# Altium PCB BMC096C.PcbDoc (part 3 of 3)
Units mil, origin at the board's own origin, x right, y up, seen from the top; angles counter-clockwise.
Board outline 5500 x 3200 mil, 4 copper layers (Top Layer, Signal Layer 1, Signal Layer 2, Bottom Layer), stack 61.6 mil thick; 174 components, 74 nets, 402 pads, 1110 vias.
Unrouted connection lines stored in the file: 741.
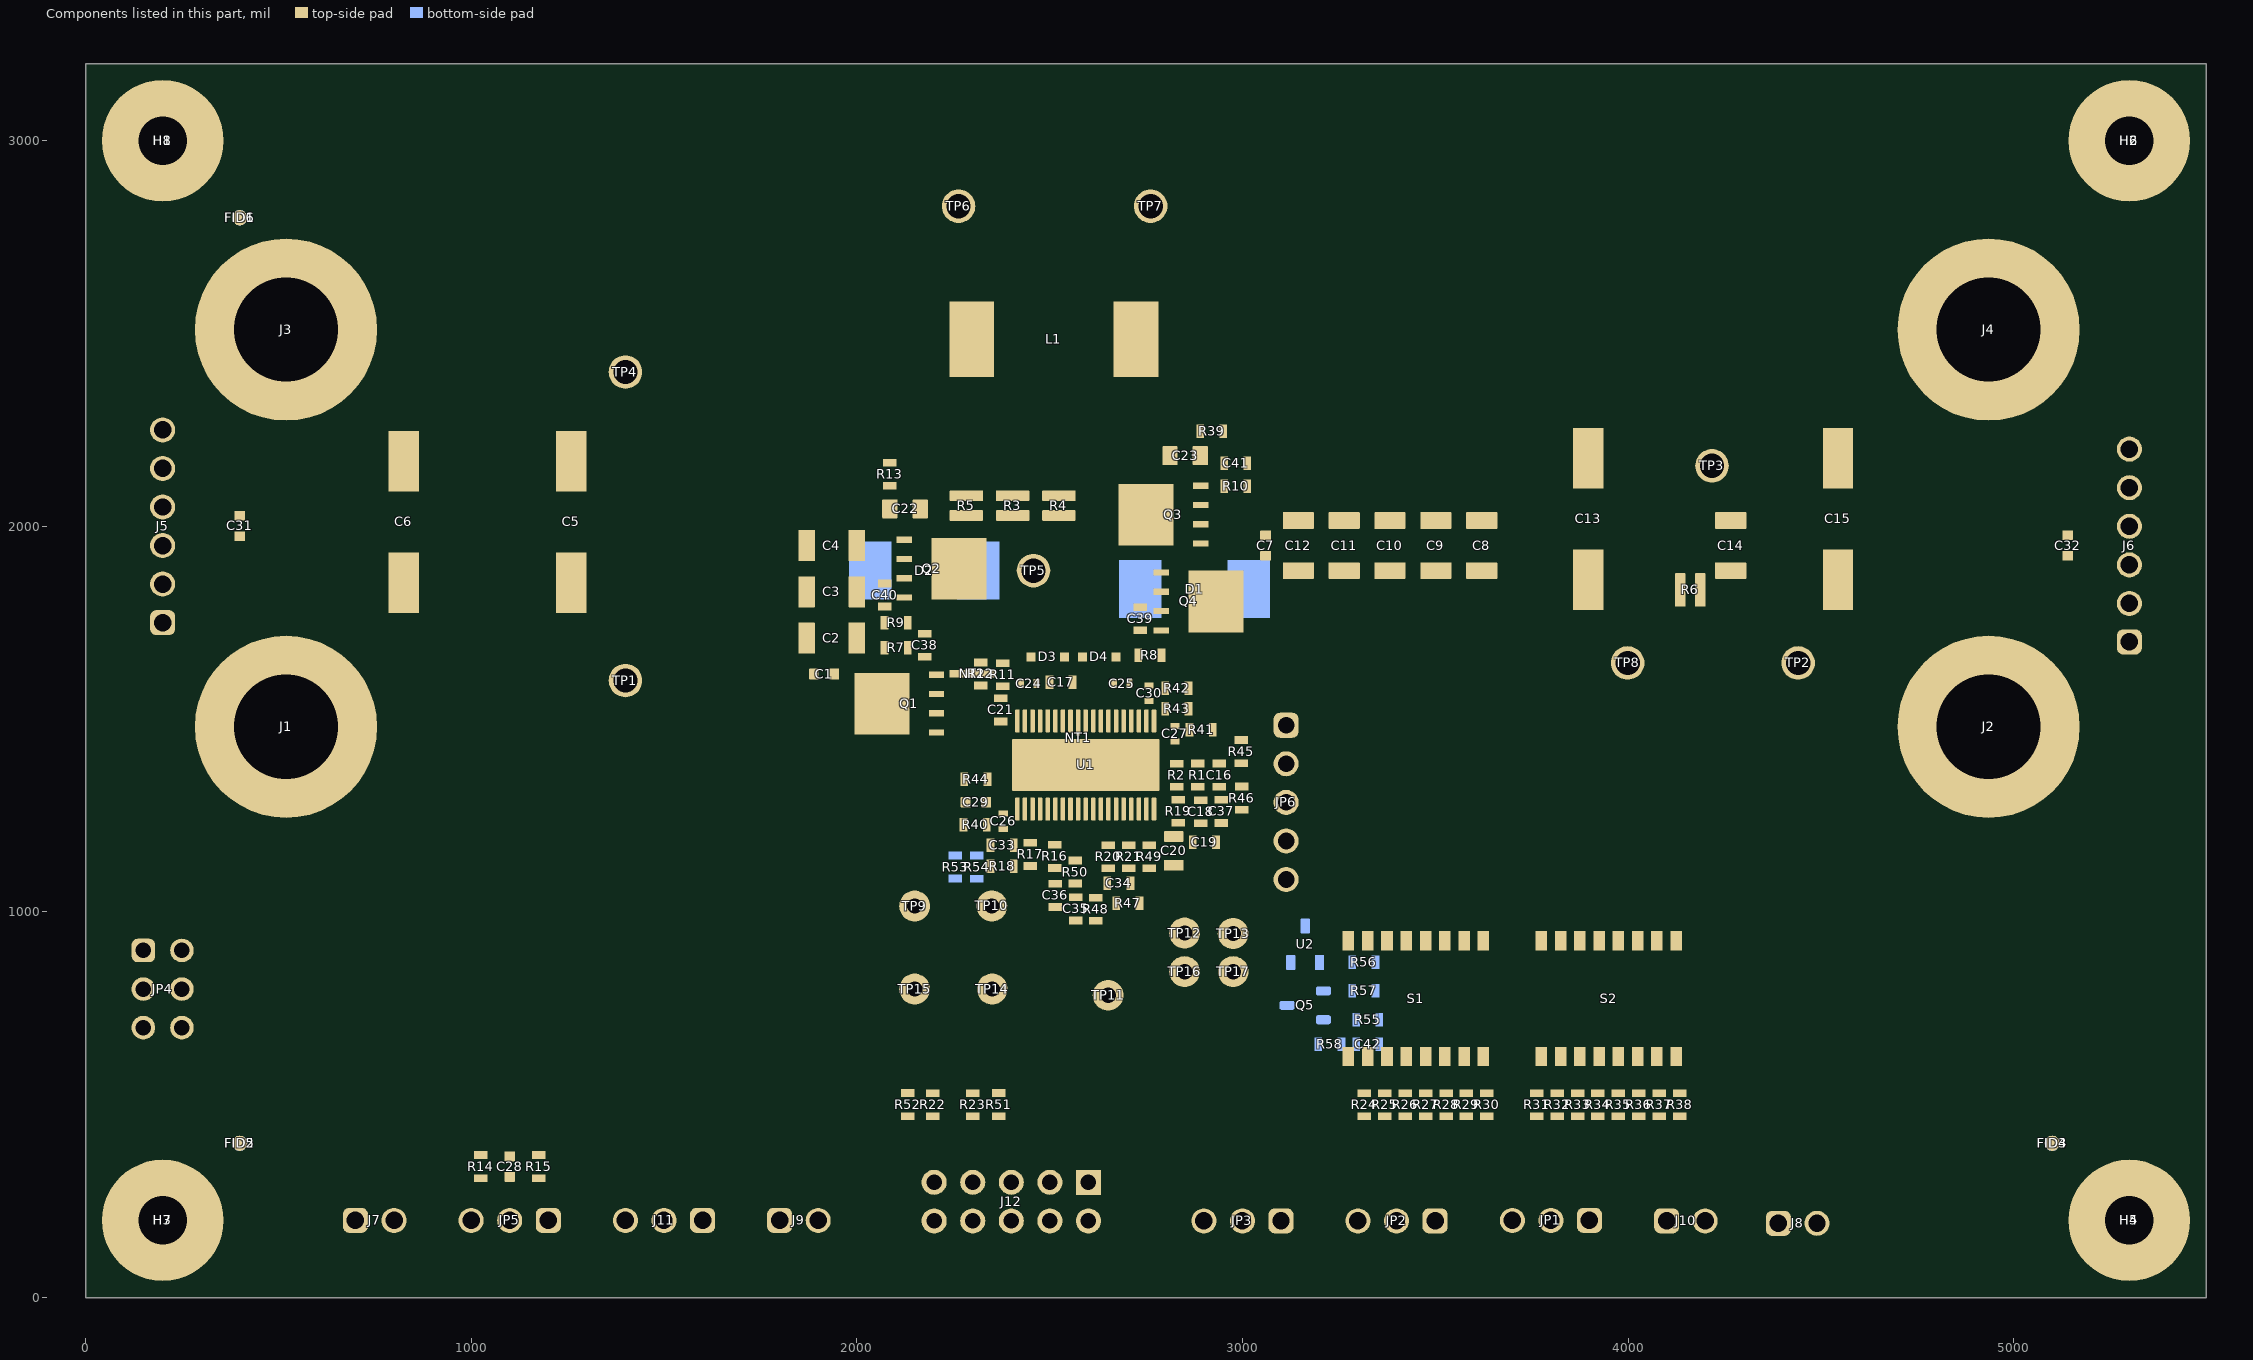
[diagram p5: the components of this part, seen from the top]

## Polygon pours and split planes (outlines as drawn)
NetC7_1 on Top Layer "TOP_LAYER_NETC7_1_P022" (solid, pour order 22): 3045.12,1944.99 4134.26,1945 cw(c4134.26,1929.75) 4149.52,1929.75 4149.52,1590.78 cw(c4121.78,1590.77) 4121.77,1563.03 2976.92,1563.04 cw(c2976.92,1676.95) 2863,1676.95 2863,1916.8 cw(c2876.2,1916.8) 2876.2,1930 3008.91,1930 ccw(c3008.91,1950.82) 3023.64,1936.1 cw(c3045.1,1914.64)
GND on Top Layer "TOP_LAYER_GND_P105" (solid, remove dead copper, pour order 105): 2411.18,1729.57 2698.43,1729.57 cw(c2698.43,1718) 2710,1718 2710,1513.56 2401.09,1513.56 2399.47,1717.76 cw(c2411.18,1717.85)
NetL1_1 on Top Layer "TOP_LAYER_NETL1_1_P021" (solid, pour order 21): 2439.03,2210.31 2595.02,2210.31 cw(c2595.03,2197.83) 2607.5,2197.83 2607.5,2065.28 cw(c2595.78,2065.28) 2595.78,2053.55 2210.26,2053.32 cw(c2210.25,2075.11) 2188.51,2076.74 cw(c2184.99,2101.56) 2161.23,2093.56 2161.23,2899.92 cw(c2173.85,2899.92) 2173.85,2912.54 2396.66,2912.54 cw(c2396.66,2899.47) 2409.73,2899.47 2409.73,2239.6 ccw(c2439.03,2239.6)
AGND on Top Layer "TOP_LAYER_AGND_P087" (solid, pour order 87): 0,1170 1836.16,1170 ccw(c1836.16,1292.93) 1923.09,1206.01 2263.77,1546.68 4143.31,1546.68 cw(c4143.31,1493.53) 4180.9,1531.11 4530.94,1181.04 5500,1181.04 5500,0 0,0
NetC22_2 on Top Layer "TOP_LAYER_NETC22_2_P067" (solid, remove dead copper, pour order 67): 2117.19,2061.84 2117.19,2035.55 ccw(c2162.32,2035.55) 2130.41,2003.64 2140.76,1993.28 2149,1985.05 cw(c2129.93,1965.98) 2156.9,1965.98 2156.9,1467.5 ccw(c2172.39,1467.5) 2172.39,1452 2230.25,1452 ccw(c2230.25,1484.72) 2253.39,1461.58 2274.94,1483.13 ccw(c2234.3,1523.77) 2291.77,1523.77 2291.77,1720.07 cw(c2321.7,1720.07) 2321.7,1750 2584.35,1750 ccw(c2584.35,1773.02) 2607.36,1773.02 2607.36,2020.89 ccw(c2584.97,2020.89) 2584.97,2043.28 2248.18,2043.28 cw(c2248.18,2092.76) 2213.2,2057.77 ccw(c2172.56,2017.14) 2172.55,2074.61 2129.96,2074.61 ccw(c2129.96,2061.84)
SW2 on Top Layer "TOP_LAYER_SW2_P019" (solid, pour order 19): 2636.76,1751.97 2832.96,1751.97 ccw(c2832.96,1768.54) 2849.53,1768.54 2849.53,2896.35 ccw(c2833.35,2896.36) 2833.35,2912.54 2636.56,2912.54 ccw(c2636.56,2894.19) 2618.22,2894.19 2618.22,1770.51 ccw(c2636.76,1770.51)
VIN on Top Layer "TOP_LAYER_VIN_P035" (solid, pour order 35): 1910.08,1982.04 1910.08,1662.97 ccw(c1928.12,1662.97) 1928.12,1644.94 2121.37,1644.94 cw(c2121.37,1630.12) 2136.18,1630.19 2136.96,1447.03 1910.55,1220.63 cw(c1834.2,1296.98) 1834.2,1189 0,1189 0,1989.64 1902.48,1989.64 cw(c1902.48,1982.04)
GND on Top Layer "TOP_LAYER_GND_P071" (solid, pour order 71): 0,3200 5500,3200 5500,1961.07 3038.58,1961.07 ccw(c3038.58,1920.9) 3010.18,1949.3 cw(c2999.05,1960.43) 2999.05,1944.7 2874.89,1944.7 cw(c2874.89,1949.59) 2870,1949.59 2870,2890.15 ccw(c2835.01,2890.15) 2835.01,2925.14 2633.22,2925.14 ccw(c2633.22,2899.43) 2607.5,2899.42 2607.5,2242.24 cw(c2590.26,2242.24) 2590.26,2225 2441.33,2225 cw(c2441.33,2242.49) 2423.84,2242.5 2423.84,2905.28 ccw(c2404.11,2905.28) 2404.11,2925 2173.69,2925 ccw(c2173.69,2896.76) 2145.45,2896.76 2145.45,1650.95 1922.11,1650.95 1922.11,1992.46 ccw(c1913.76,1992.46) 1913.75,2000.81 0,2000.81
VOUT on Top Layer "TOP_LAYER_VOUT_P024" (solid, pour order 24): 4173.03,1594.62 4173.03,1930.34 cw(c4187.69,1930.34) 4187.69,1945 5500,1945 5500,1196 4580.52,1196 cw(c4580.52,1298.35) 4508.15,1225.98 4196.74,1537.4 cw(c4253.96,1594.62)
AGND on Signal Layer 1 "SIGNAL_LAYER_1_AGND_P100" (solid, pour order 100): -3.94,1170.33 1883.14,1170.33 2216.83,1504.02 2888.75,1503.8 ccw(c2888.76,1531.21) 2908.14,1511.82 cw(c2993.09,1426.87) 2993.09,1547.01 4139.37,1547.01 cw(c4139.38,1493.89) 4176.96,1531.44 4499.24,1209.13 ccw(c4566.25,1276.14) 4566.25,1181.37 5496.06,1181.37 5496.06,0.33 -3.94,0.33
GND on Signal Layer 1 "SIGNAL_LAYER_1_GND_P106" (solid, remove dead copper, pour order 106): 2302.71,1728.98 2842.03,1728.98 2842.03,1531.8 cw(c2823.78,1531.8) 2823.78,1513.56 2321.84,1513.56 cw(c2321.84,1532.68) 2302.71,1532.68
VOUT on Signal Layer 1 "SIGNAL_LAYER_1_VOUT_P103" (solid, pour order 103): 4173.03,1594.62 4173.03,1899.2 cw(c4202.83,1899.2) 4202.83,1929 5500,1929 5500,1196 4580.52,1196 cw(c4580.52,1298.35) 4508.15,1225.98 4196.74,1537.4 cw(c4253.96,1594.62)
GND on Signal Layer 1 "SIGNAL_LAYER_1_GND_P098" (solid, pour order 98): 0,3200 5500,3200 5500,1955 3082.67,1955 3075.17,1947.5 2886.53,1947.5 cw(c2886.53,1964.03) 2870,1964.03 2870,2890.15 ccw(c2835.01,2890.15) 2835.01,2925.14 2633.22,2925.14 ccw(c2633.21,2899.43) 2607.5,2899.42 2607.5,2242.24 cw(c2590.27,2242.24) 2590.26,2225 2441.33,2225 cw(c2441.33,2242.49) 2423.84,2242.5 2423.84,2905.28 ccw(c2404.11,2905.28) 2404.11,2925 2173.69,2925 ccw(c2173.69,2896.76) 2145.45,2896.76 2145.45,1664.69 2026.67,1664.55 cw(c2026.61,1706.18) 1997.13,1676.79 1979.27,1694.71 cw(c2034.96,1750.2) 1956.34,1750.2 1956.34,2011.85 ccw(c1932.65,2011.85) 1932.65,2035.55 0,2035.55
SW2 on Signal Layer 1 "SIGNAL_LAYER_1_SW2_P094" (solid, pour order 94): 2636.76,1751.97 2802.07,1751.97 ccw(c2802.07,1772.11) 2822.22,1772.11 2822.22,2086.35 cw(c2847.39,2086.35) 2829.59,2104.15 2839.32,2113.88 ccw(c2812.48,2140.71) 2850.44,2140.76 2849.53,2896.36 ccw(c2833.35,2896.36) 2833.35,2912.54 2636.56,2912.54 ccw(c2636.56,2894.2) 2618.22,2894.19 2618.22,1770.51 ccw(c2636.76,1770.51)
NetL1_1 on Signal Layer 1 "SIGNAL_LAYER_1_NETL1_1_P092" (solid, pour order 92): 2439.03,2210.31 2595.02,2210.31 cw(c2595.03,2197.83) 2607.5,2197.83 2607.5,2065.28 cw(c2595.78,2065.28) 2595.78,2053.55 2210.26,2053.32 cw(c2210.25,2075.11) 2195.9,2058.71 2168.48,2082.69 cw(c2184.99,2101.56) 2161.23,2093.56 2161.23,2899.92 cw(c2173.85,2899.92) 2173.85,2912.54 2396.66,2912.54 cw(c2396.66,2899.47) 2409.73,2899.47 2409.73,2239.6 ccw(c2439.03,2239.6)
NetC22_2 on Signal Layer 1 "SIGNAL_LAYER_1_NETC22_2_P076" (solid, remove dead copper, pour order 76): 2117.19,2061.84 2117.19,2035.55 ccw(c2162.32,2035.55) 2130.41,2003.64 2140.76,1993.28 2149,1985.05 cw(c2129.93,1965.98) 2156.9,1965.98 2156.9,1467.5 ccw(c2172.39,1467.5) 2172.39,1452 2230.25,1452 ccw(c2230.25,1484.72) 2253.39,1461.58 2274.94,1483.13 ccw(c2234.3,1523.77) 2291.77,1523.77 2291.77,1720.07 cw(c2321.7,1720.07) 2321.7,1750 2584.35,1750 ccw(c2584.35,1773.02) 2607.36,1773.02 2607.36,2020.89 ccw(c2584.97,2020.89) 2584.97,2043.28 2248.18,2043.28 cw(c2248.18,2092.76) 2213.2,2057.77 ccw(c2172.56,2017.14) 2172.55,2074.61 2129.96,2074.61 ccw(c2129.96,2061.84)
VIN on Signal Layer 1 "SIGNAL_LAYER_1_VIN_P055" (solid, pour order 55): 1910.08,1971.55 1910.08,1662.97 ccw(c1928.12,1662.97) 1928.12,1644.94 2115.05,1644.94 cw(c2115.05,1623.77) 2136.21,1623.86 2136.87,1468.16 cw(c2086.16,1467.95) 2122.01,1432.09 1901.65,1211.73 cw(c1846.78,1266.61) 1846.78,1189 0,1189 0,1989.64 1891.99,1989.64 cw(c1891.99,1971.55)
NetC7_1 on Signal Layer 1 "SIGNAL_LAYER_1_NETC7_1_P072" (solid, pour order 72): 2884.91,1927.67 4142.5,1927.67 cw(c4142.5,1908.6) 4161.57,1908.6 4161.57,1602.95 2885.77,1602.95 cw(c2885.77,1614.86) 2873.87,1614.86 2873.87,1916.63 cw(c2884.91,1916.63)
AGND on Bottom Layer "BOTTOM_LAYER_AGND_P113" (solid, pour order 113): -3.94,1170.33 1883.14,1170.33 2216.83,1504.02 2888.75,1503.8 ccw(c2888.76,1531.21) 2908.14,1511.82 cw(c2993.09,1426.87) 2993.09,1547.01 4139.23,1547.01 cw(c4139.38,1493.89) 4176.96,1531.44 4527,1181.37 5496.06,1181.37 5496.06,0.33 -3.94,0.33
GND on Bottom Layer "BOTTOM_LAYER_GND_P108" (solid, remove dead copper, pour order 108): 2321.61,1728.98 2837.53,1728.98 cw(c2837.53,1709.95) 2856.56,1709.95 2856.56,1532.25 cw(c2837.87,1532.25) 2837.87,1513.56 2313.92,1513.56 cw(c2313.92,1524.76) 2302.71,1524.76 2302.71,1710.09 cw(c2321.61,1710.09)
VOUT on Bottom Layer "BOTTOM_LAYER_VOUT_P104" (solid, pour order 104): 4173.03,1594.62 4173.03,1930.34 cw(c4187.69,1930.34) 4187.69,1945 5500,1945 5500,1196 4580.52,1196 cw(c4580.52,1298.35) 4508.15,1225.98 4196.74,1537.4 cw(c4253.96,1594.62)
GND on Bottom Layer "BOTTOM_LAYER_GND_P099" (solid, pour order 99): 0,3200 5500,3200 5500,1960.63 3031.97,1960.63 ccw(c3031.97,1925.67) 3012.75,1954.88 cw(c2988.11,1992.34) 2988.11,1947.5 2887.9,1947.5 cw(c2887.9,1965.4) 2870,1965.4 2870,2890.15 ccw(c2835.01,2890.15) 2835.01,2925.14 2633.22,2925.14 ccw(c2633.22,2899.43) 2607.5,2899.42 2607.5,2242.24 cw(c2590.26,2242.24) 2590.26,2225 2441.33,2225 cw(c2441.33,2242.49) 2423.84,2242.5 2423.84,2905.28 ccw(c2404.11,2905.28) 2404.11,2925 2173.69,2925 ccw(c2173.69,2896.76) 2145.45,2896.76 2145.45,1650.95 1922.11,1650.95 1922.11,1992.46 ccw(c1913.76,1992.46) 1913.75,2000.81 0,2000.81
SW2 on Bottom Layer "BOTTOM_LAYER_SW2_P095" (solid, pour order 95): 2636.76,1751.97 2832.96,1751.97 ccw(c2832.96,1768.54) 2849.53,1768.54 2849.53,2896.35 ccw(c2833.35,2896.36) 2833.35,2912.54 2636.56,2912.54 ccw(c2636.56,2894.19) 2618.22,2894.19 2618.22,1770.51 ccw(c2636.76,1770.51)
NetL1_1 on Bottom Layer "BOTTOM_LAYER_NETL1_1_P093" (solid, pour order 93): 2439.03,2210.31 2595.02,2210.31 cw(c2595.03,2197.83) 2607.5,2197.83 2607.5,2065.28 cw(c2595.78,2065.28) 2595.78,2053.55 2210.26,2053.32 cw(c2210.25,2075.11) 2188.51,2076.74 cw(c2184.99,2101.56) 2161.23,2093.56 2161.23,2899.92 cw(c2173.85,2899.92) 2173.85,2912.54 2396.66,2912.54 cw(c2396.66,2899.47) 2409.73,2899.47 2409.73,2239.6 ccw(c2439.03,2239.6)
NetC22_2 on Bottom Layer "Top Layer-NetC22_2" (solid, remove dead copper, pour order 20): 2117.19,2061.84 2117.19,2035.55 ccw(c2162.32,2035.55) 2130.41,2003.64 2140.76,1993.28 2149,1985.05 cw(c2129.93,1965.98) 2156.9,1965.98 2156.9,1467.5 ccw(c2172.39,1467.5) 2172.39,1452 2230.25,1452 ccw(c2230.25,1484.72) 2253.39,1461.58 2274.94,1483.13 ccw(c2234.3,1523.77) 2291.77,1523.77 2291.77,1720.07 cw(c2321.7,1720.07) 2321.7,1750 2584.35,1750 ccw(c2584.35,1773.02) 2607.36,1773.02 2607.36,2020.89 ccw(c2584.97,2020.89) 2584.97,2043.28 2248.18,2043.28 cw(c2248.18,2092.76) 2213.2,2057.77 ccw(c2172.56,2017.14) 2172.55,2074.61 2129.96,2074.61 ccw(c2129.96,2061.84)
VIN on Bottom Layer "BOTTOM_LAYER_VIN_P078" (solid, pour order 78): 1910.08,1989.64 1910.08,1644.94 2136.12,1644.94 2136.96,1447.03 1878.92,1189 0,1189 0,1989.64
NetC7_1 on Bottom Layer "BOTTOM_LAYER_NETC7_1_P062" (solid, pour order 62): 3042.41,1945 4141.36,1945 cw(c4141.37,1924.8) 4161.57,1924.8 4161.57,1584.22 cw(c4143.89,1584.22) 4143.89,1566.54 2881.88,1566.54 cw(c2881.88,1578.43) 2870,1578.43 2870,1905.77 cw(c2894.23,1905.77) 2894.23,1930 3006.2,1930 ccw(c3006.2,1949.43) 3019.94,1935.69 cw(c3042.41,1913.22)
AGND on Signal Layer 2 "SIGNAL_LAYER_2_AGND_P111" (solid, pour order 111): 36.77,1152.24 1892.17,1152.24 ccw(c1892.17,1228.72) 1946.25,1174.64 2257.54,1485.93 2929.46,1485.7 ccw(c2929.47,1513.12) 2948.85,1493.73 cw(c3033.8,1408.78) 3033.8,1528.92 4179.94,1528.92 cw(c4180.09,1475.8) 4217.67,1513.35 4553.28,1177.71 ccw(c4588.11,1212.54) 4588.11,1163.28 5536.77,1163.28 5536.77,-17.76 36.77,-17.76
GND on Signal Layer 2 "SIGNAL_LAYER_2_GND_P112" (solid, pour order 112): 0,3200 5500,3200 5500,1196.94 4549.63,1196.94 cw(c4549.63,1256.88) 4507.25,1214.5 4209.92,1511.82 2210.35,1511.82 1902.06,1203.79 cw(c1846.27,1259.63) 1846.27,1180.69 0,1180.69

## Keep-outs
Keep-Out Layer:
  text ".Layer_Name" at 577,-858.49 h60

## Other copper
Top Layer:
  pour cut-out: 5258.88,1899.76 ccw(c5300.24,1899.76) 5300.24,1858.41 ccw(c5300.24,1899.76) 5341.59,1899.76 ccw(c5300.24,1899.76) 5300.24,1941.11 ccw(c5300.24,1899.76)
  pour cut-out: 5258.4,2000.28 ccw(c5299.75,2000.28) 5299.75,1958.93 ccw(c5299.75,2000.28) 5341.11,2000.28 ccw(c5299.75,2000.28) 5299.75,2041.63 ccw(c5299.75,2000.28)
  pour cut-out: 158.75,2049.72 ccw(c200.1,2049.72) 200.1,2008.37 ccw(c200.1,2049.72) 241.46,2049.72 ccw(c200.1,2049.72) 200.1,2091.07 ccw(c200.1,2049.72)
  pour cut-out: 158.17,1950.33 ccw(c199.52,1950.33) 199.52,1908.97 ccw(c199.52,1950.33) 240.87,1950.33 ccw(c199.52,1950.33) 199.52,1991.68 ccw(c199.52,1950.33)
  text ".Layer_Name" at 577,-858.49 h60
Signal Layer 1:
  pour cut-out: 1875.85,1679.99 ccw(c1897.35,1679.99) 1897.35,1658.48 ccw(c1897.35,1679.99) 1918.86,1679.99 ccw(c1897.35,1679.99) 1897.35,1701.5 ccw(c1897.35,1679.99)
  pour cut-out: 1950.34,1679.99 ccw(c1971.85,1679.99) 1971.85,1658.48 ccw(c1971.85,1679.99) 1993.36,1679.99 ccw(c1971.85,1679.99) 1971.85,1701.5 ccw(c1971.85,1679.99)
  pour cut-out: 3038.49,1905 ccw(c3060,1905) 3060,1883.49 ccw(c3060,1905) 3081.51,1905 ccw(c3060,1905) 3060,1926.51 ccw(c3060,1905)
  pour cut-out: 4164.13,1786.45 ccw(c4185.64,1786.45) 4185.64,1764.94 ccw(c4185.64,1786.45) 4207.15,1786.45 ccw(c4185.64,1786.45) 4185.64,1807.96 ccw(c4185.64,1786.45)
  pour cut-out: 4114.13,1786.45 ccw(c4135.64,1786.45) 4135.64,1764.94 ccw(c4135.64,1786.45) 4157.15,1786.45 ccw(c4135.64,1786.45) 4135.64,1807.96 ccw(c4135.64,1786.45)
  pour cut-out: 3038.49,1995 ccw(c3060,1995) 3060,1973.49 ccw(c3060,1995) 3081.51,1995 ccw(c3060,1995) 3060,2016.51 ccw(c3060,1995)
  pour cut-out: 5258.88,1899.76 ccw(c5300.24,1899.76) 5300.24,1858.41 ccw(c5300.24,1899.76) 5341.59,1899.76 ccw(c5300.24,1899.76) 5300.24,1941.11 ccw(c5300.24,1899.76)
  pour cut-out: 5258.4,2000.28 ccw(c5299.75,2000.28) 5299.75,1958.93 ccw(c5299.75,2000.28) 5341.11,2000.28 ccw(c5299.75,2000.28) 5299.75,2041.63 ccw(c5299.75,2000.28)
  pour cut-out: 158.75,2049.72 ccw(c200.1,2049.72) 200.1,2008.37 ccw(c200.1,2049.72) 241.46,2049.72 ccw(c200.1,2049.72) 200.1,2091.07 ccw(c200.1,2049.72)
  pour cut-out: 158.17,1950.33 ccw(c199.52,1950.33) 199.52,1908.97 ccw(c199.52,1950.33) 240.87,1950.33 ccw(c199.52,1950.33) 199.52,1991.68 ccw(c199.52,1950.33)
  pour cut-out: 3081.51,1999.28 3081.51,1997.36 3106.87,1972 5253.06,1972 5277.26,1996.21 5296.16,1977.3 5298.2,1977.3 5298.2,1976.42 5263.86,1942.08 3088.72,1942.08 3055.72,1975.08 3055.72,1986.77
  pour cut-out: 4197,1779 4197.82,1778.18 4197.82,1754.06 4185.64,1741.88 4185.64,1636.27 4167.41,1618.04 4147.82,1637.62 4147.82,1643.5 4155.65,1651.33 4155.65,1756.46 4184.19,1785 4186.29,1785
  text ".Layer_Name" at 577.07,-859.59 h60
Signal Layer 2:
  pour cut-out: 1950.34,1679.99 ccw(c1971.85,1679.99) 1971.85,1658.48 ccw(c1971.85,1679.99) 1993.36,1679.99 ccw(c1971.85,1679.99) 1971.85,1701.5 ccw(c1971.85,1679.99)
  pour cut-out: 3038.49,1995.13 ccw(c3060,1995.13) 3060,1973.62 ccw(c3060,1995.13) 3081.51,1995.13 ccw(c3060,1995.13) 3060,2016.64 ccw(c3060,1995.13)
  pour cut-out: 5258.88,1899.76 ccw(c5300.24,1899.76) 5300.24,1858.41 ccw(c5300.24,1899.76) 5341.59,1899.76 ccw(c5300.24,1899.76) 5300.24,1941.11 ccw(c5300.24,1899.76)
  pour cut-out: 5258.4,2000.28 ccw(c5299.75,2000.28) 5299.75,1958.93 ccw(c5299.75,2000.28) 5341.11,2000.28 ccw(c5299.75,2000.28) 5299.75,2041.63 ccw(c5299.75,2000.28)
  pour cut-out: 158.75,2049.72 ccw(c200.1,2049.72) 200.1,2008.37 ccw(c200.1,2049.72) 241.46,2049.72 ccw(c200.1,2049.72) 200.1,2091.07 ccw(c200.1,2049.72)
  pour cut-out: 158.17,1950.33 ccw(c199.52,1950.33) 199.52,1908.97 ccw(c199.52,1950.33) 240.87,1950.33 ccw(c199.52,1950.33) 199.52,1991.68 ccw(c199.52,1950.33)
  text ".Layer_Name" at 575.75,-859.59 h60
Bottom Layer:
  pour cut-out: 1950.34,1679.99 ccw(c1971.85,1679.99) 1971.85,1658.48 ccw(c1971.85,1679.99) 1993.36,1679.99 ccw(c1971.85,1679.99) 1971.85,1701.5 ccw(c1971.85,1679.99)
  pour cut-out: 1875.97,1680.26 ccw(c1897.48,1680.26) 1897.48,1658.75 ccw(c1897.48,1680.26) 1918.99,1680.26 ccw(c1897.48,1680.26) 1897.48,1701.76 ccw(c1897.48,1680.26)
  pour cut-out: 4165.05,1785.33 ccw(c4186.56,1785.33) 4186.56,1763.82 ccw(c4186.56,1785.33) 4208.07,1785.33 ccw(c4186.56,1785.33) 4186.56,1806.83 ccw(c4186.56,1785.33)
  pour cut-out: 4115.05,1785.33 ccw(c4136.56,1785.33) 4136.56,1763.82 ccw(c4136.56,1785.33) 4158.07,1785.33 ccw(c4136.56,1785.33) 4136.56,1806.83 ccw(c4136.56,1785.33)
  pour cut-out: 3038.84,1994.97 ccw(c3060.34,1994.97) 3060.34,1973.46 ccw(c3060.34,1994.97) 3081.85,1994.97 ccw(c3060.34,1994.97) 3060.34,2016.48 ccw(c3060.34,1994.97)
  pour cut-out: 5258.4,2000.28 ccw(c5299.75,2000.28) 5299.75,1958.93 ccw(c5299.75,2000.28) 5341.11,2000.28 ccw(c5299.75,2000.28) 5299.75,2041.63 ccw(c5299.75,2000.28)
  pour cut-out: 5258.88,1899.76 ccw(c5300.24,1899.76) 5300.24,1858.41 ccw(c5300.24,1899.76) 5341.59,1899.76 ccw(c5300.24,1899.76) 5300.24,1941.11 ccw(c5300.24,1899.76)
  pour cut-out: 158.17,1950.33 ccw(c199.52,1950.33) 199.52,1908.97 ccw(c199.52,1950.33) 240.87,1950.33 ccw(c199.52,1950.33) 199.52,1991.68 ccw(c199.52,1950.33)
  pour cut-out: 158.75,2049.72 ccw(c200.1,2049.72) 200.1,2008.37 ccw(c200.1,2049.72) 241.46,2049.72 ccw(c200.1,2049.72) 200.1,2091.07 ccw(c200.1,2049.72)
  text ".Layer_Name" at 577,-858.49 h60

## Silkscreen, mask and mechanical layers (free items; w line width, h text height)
Top Overlay:
  lines w10: 3442.22,1039.95 3618.92,1039.95 3620.57,1041.6 3620.57,1527.57 3619.26,1528.89 3442.22,1528.89 3442.22,1039.95
  text "CSB" at 2216.08,2931 h35
  text "SW2" at 2706,2929 h35
  text "GND" at 4170.29,2252.84 h35
  text "GND" at 279.34,2174.75 h35
  text "GND" at 5146,2131.71 h35
  text "S-" at 279.57,2030.73 h35
  text "S-" at 5180.88,1988.53 h35
  text "S+" at 282.39,1933.37 h35
  text "S+" at 5180.88,1879.92 h35
  text "CSA" at 2546.08,1872 h35
  text "VIN" at 271.64,1785.47 h35
  text "VOUT" at 5112.82,1735.47 h35
  text "4-36V" at 81,1640 h35
  text "16V" at 5263.92,1608.92 h35
  text "Max.10A" at 56,1586.61 h35
  text "Max.9.4A" at 5187.22,1559.78 h35
  text "JP6" at 3474.04,1549.43 h35
  text "ISNSP" at 3928,1512.5 h35
  text "VOUT" at 4383.52,1512.5 h35
  text "AC_A" at 3468.04,1468.17 h35
  text "AC_B" at 3468.04,1376.48 h35
  text "AGND" at 3468.04,1268.64 h35
  text "R_FB" at 3468.04,1164.83 h35
  text "VCC" at 3468.04,1065.79 h35
  text ".PRJ_title" at 4383.92,971.49 h60
  text "SS/" at 2691.75,947.1 h35
  text "COMP" at 3038.46,931.91 h35
  text "VBIAS" at 2056.66,916.91 h35
  text "VCC" at 2295.08,910.91 h35
  text "ATRK" at 2657.86,890.71 h35
  text "'.PRJ_Number'" at 4383.45,889.17 h40
  text "VEXT" at 341.29,886.83 h35
  text "REV..PCB_Rev" at 4384.8,814.58 h40
  text "VIN" at 341.29,786.83 h35
  text "AGND" at 2857.25,743.23 h35
  text "SDA" at 2101.92,702 h35
  text "SCL" at 2316.76,702 h35
  text "VOUT" at 339.29,686.83 h35
  text "SYNC" at 2588,676 h35
  text "VIN" at 1010.4,456 h35 r90
  text "EN/UVLO" at 1110.4,456 h35 r90
  text "GND" at 1219,456 h35 r90
  text "GND" at 819,295.5 h35 r90
  text "VCC" at 1419,295.5 h35 r90
  text "FLT" at 1819,295.5 h35 r90
  text "VEXT" at 719,291.5 h35 r90
  text "IMONOUT" at 1519,291.5 h35 r90
  text "GND" at 1619,288.76 h35 r90
  text "GND" at 1919,285.5 h35 r90
  text "VCC" at 3719,281 h35 r90
  text "MODE" at 3810.4,281 h35 r90
  text "GND" at 3919,281 h35 r90
  text "RT" at 4119,281 h35 r90
  text "GND" at 4219,281 h35 r90
  text "GND" at 4509,279.77 h35 r90
  text "VCC" at 3319,278.69 h35 r90
  text "SYNC" at 3412.9,278.69 h35 r90
  text "GND" at 3514,278.69 h35 r90
  text "VCC" at 2918,273.14 h35 r90
  text "CFG" at 4407.09,271.64 h35 r90
  text "DTRK" at 3014,270.78 h35 r90
  text "GND" at 3119.04,271.17 h35 r90
  text ".Layer_Name" at 577,-858.49 h60
Bottom Overlay:
  text ".Layer_Name" at 577,-858.49 h60
Top Paste:
  text ".Layer_Name" at 577,-858.49 h60
Bottom Paste:
  text ".Layer_Name" at 577,-858.49 h60
Top Solder:
  text ".Layer_Name" at 577,-858.49 h60
  text ".Layer_Name" at 577,-858.49 h60
Bottom Solder:
  text ".Layer_Name" at 577,-858.49 h60
Drill Guide:
  text ".Layer_Name" at 577,-858.49 h60
M1 Board Outline:
  the board outline again, w10
  text ".Layer_Name" at 577,-858.49 h60
M2 Board Dimensions:
  rectangle: 0,-275 125,-150
  rectangle: 125,-400 500,-275
  lines w7: 0,-275 1000,-275 ; 125,-400 125,-150 ; 250,-400 250,-150 ; 500,-400 500,-150 ; 750,-400 750,-150 ; 0,-400 1000,-400 1000,-150 0,-150 0,-400
  text ".Layer_Name" at 577,-858.49 h60
M3 3D STEP Top:
  text ".Layer_Name" at 577,-858.49 h60
M4 3D STEP Bottom:
  text ".Layer_Name" at 577,-858.49 h60
M5 Assembly Top:
  lines w10: -292,-930.17 6308,-930.17 ; -292,-726.83 6310,-726.83 ; -292,-523.5 -292,-1133.5 3713,-1133.5 6310,-1133.5 6310,-523.5 -291.5,-523.5 -291.5,-1133.5 1284,-1133.5 ; 2173,-1133.5 2173,-523.5 ; 3440,-726.83 3440,-523.5 ; 4280,-726.83 4280,-523.5 ; 4902,-1140 4902,-937.17
  text "COMPONENTS MARKED 'DNP' SHOULD NOT BE POPULATED." at 1153.5,-318.5 h60
  text "ASSEMBLY VARIANT:" at 1153,-434 h60
  text ".VariantName" at 2189,-434 h60
  text "PCB VIEWED FROM TOP SIDE" at -228.5,-655.67 h60
  text "BOARD #:" at 2248,-655.67 h60
  text ".PRJ_Number" at 2793.5,-655.67 h60
  text "REV:" at 3638,-655.67 h60
  text ".PCB_Rev" at 3929.5,-655.67 h60
  text "SVN REV:" at 4476,-655.67 h60
  text ".VersionControl_RevNumber" at 4982,-655.67 h60
  text "TID #:" at 2248,-859 h60
  text ".TID" at 2793.5,-859 h60
  text "PLOT NAME =" at -228.5,-1064.34 h60
  text ".plot_File_Name" at 577,-1064.34 h60
  text "GENERATED    :" at 2250,-1064.34 h60
  text ".Print_Date" at 3119.5,-1064.34 h60
  text ".Print_Time" at 3848.5,-1064.34 h60
  text "TEXAS INSTRUMENTS" at 5113,-1064.34 h60
M6 Assembly Bottom:
  lines w10: -292.5,-727.33 6309.5,-727.33 ; -290.5,-930.67 6309.5,-930.67 ; 1115.5,-1140.5 1115.5,-937.67 ; 1737.5,-727.33 1737.5,-524 ; 2577.5,-727.33 2577.5,-524 ; 3844.5,-1134 3844.5,-524 ; 4733.5,-1134 6309,-1134 6309,-524 -292.5,-524 -292.5,-1134 2304.5,-1134 6309.5,-1134 6309.5,-524
  text "COMPONENTS MARKED 'DNP' SHOULD NOT BE POPULATED." at 6102,-318 h60
  text ".VariantName" at 5058,-434 h60
  text "ASSEMBLY VARIANT:" at 6097,-434 h60
  text ".VersionControl_RevNumber" at 1035.5,-656.17 h60
  text "SVN REV:" at 1541.5,-656.17 h60
  text ".PCB_Rev" at 2088,-656.17 h60
  text "REV:" at 2379.5,-656.17 h60
  text ".PRJ_Number" at 3224,-656.17 h60
  text "BOARD #:" at 3769.5,-656.17 h60
  text "PCB VIEWED FROM BOTTOM SIDE" at 6246,-656.17 h60
  text ".TID" at 3224,-859.5 h60
  text "TID #:" at 3769.5,-859.5 h60
  text "TEXAS INSTRUMENTS" at 904.5,-1064.84 h60
  text ".Print_Time" at 2169,-1064.84 h60
  text ".Print_Date" at 2898,-1064.84 h60
  text "GENERATED    :" at 3767.5,-1064.84 h60
  text ".plot_File_Name" at 5440.5,-1064.84 h60
  text "PLOT NAME =" at 6246,-1064.84 h60
M9 Title Sheet:
  lines w10: -491.5,1041.5 -291.5,1041.5 ; -491.5,3416.5 -291.5,3416.5 ; -491.5,5791.5 -291.5,5791.5 ; 2008.5,-1333.5 2008.5,-1133.5 ; 2008.5,7966.5 2008.5,8166.5 ; 4508.5,-1333.5 4508.5,-1133.5 ; 4508.5,7966.5 4508.5,8166.5 ; 6321,-1133.5 6321,-523.5 11303.5,-523.5 ; 7008.5,-1333.5 7008.5,-1133.5 ; 7008.5,7966.5 7008.5,8166.5 ; 9508.5,-1333.5 9508.5,-1133.5 ; 9508.5,7966.5 9508.5,8166.5 ; 11303.5,-1133.5 11303.5,-523.5 ; 11303.5,-823.5 14303.5,-823.5 ; 11303.5,-223.5 14303.5,-223.5 ; 11304.5,370.5 14304.5,370.5 ; 12008.5,-1333.5 12008.5,-1133.5 ; 12008.5,7966.5 12008.5,8166.5 ; 12808.5,-1123.5 12808.5,-523.5 ; 14303.5,-523.5 11303.5,-523.5 ; 14303.5,76.5 11303.5,76.5 ; 14308.5,66.5 14308.5,-1133.5 ; 14308.5,871 11304.5,871 11303.5,871 11303.5,370.5 11303.5,76.5 ; 14308.5,1041.5 14508.5,1041.5 ; 14308.5,3416.5 14508.5,3416.5 ; 14308.5,5791.5 14508.5,5791.5 ; 11303.5,-523.5 11303.5,76.5 ; 14308.5,-1133.5 14308.5,7966.5 -291.5,7966.5 -291.5,-1133.5 14308.5,-1133.5 ; -491.5,-1333.5 -491.5,8166.5 14508.5,8166.5 14508.5,-1333.5 -491.5,-1333.5
  text "1" at 739.84,8036.5 h70
  text "2" at 3235.5,8036.5 h70
  text "3" at 5724.84,8036.5 h70
  text "4" at 8231.51,8036.5 h70
  text "5" at 10730.5,8036.5 h70
  text "6" at 13235.5,8036.5 h70
  text "A" at -416.5,6893.5 h70
  text "A" at 14383.5,6893.5 h70
  text "B" at -416.5,4513.5 h70
  text "B" at 14383.5,4513.5 h70
  text "C" at -416.5,2138.5 h70
  text "C" at 14383.5,2138.5 h70
  text "PROJECT TITLE:" at 11343.5,277.5 h45
  text ".PRJ_Title" at 11393.5,144.17 h70
  text "DESIGNED FOR:" at 11343.5,-23.5 h45
  text ".PRJ_Customer" at 11393.5,-163.5 h70
  text "D" at -416.5,-231.5 h70
  text "D" at 14383.5,-231.5 h70
  text "FILE NAME:" at 11343.5,-323.5 h45
  text ".PCB_File_Name_No_Path" at 11393.5,-443.5 h70
  text "Texas Instruments (TI) and/or its licensors do not warrant the accuracy or completeness of this specification" at 6374,-605.34 h45
  text "ENGINEER:" at 11343.5,-613.5 h45
  text "LAYOUT BY:" at 12848.5,-613.5 h45
  text "or any information contained therein. TI and/or its licensors do not warrant that this design will meet" at 6329.01,-718 h45
  text ".PRJ_Engineer" at 11393.5,-768.49 h70
  text ".PCB_Layout" at 12899,-768.49 h70
  text "the specifications, will be suitable for your application or fit for any particular purpose, or will operate in" at 6329.01,-830.67 h45
  text ".Layer_Name" at 577,-858.49 h60
  text "ALTIUM DESIGNER VERSION:" at 12848.5,-923.5 h45
  text "an implementation. TI and/or its licensors do not warrant that the design is production worthy. You should" at 6329.01,-943.33 h45
  text "completely validate and test your design implementation to confirm the system functionality for your application." at 6374,-1056 h45
  text ".print_Scale" at 11393.5,-1056.83 h70
  text ".Application_BuildNumber" at 12899,-1056.83 h70
  text "1" at 739.84,-1263.5 h70
  text "2" at 3235.5,-1263.5 h70
  text "3" at 5724.84,-1263.5 h70
  text "4" at 8231.51,-1263.5 h70
  text "5" at 10730.5,-1263.5 h70
  text "6" at 13235.5,-1263.5 h70
M10 Fab Notes:
  drawing of 189 lines, arcs and shapes, not listed
  text "DESIGN INFORMATION" at 12382.02,6356.17 h60
  text "MIN. TRACK WIDTH:" at 11737.46,6224.05 h60
  text "8" at 12833.7,6224.05 h60
  text "MIL" at 12988.46,6224.05 h60
  text "7.874" at 12667.32,6102.36 h60
  text "MIN. CLEARANCE:" at 11737.46,6099.92 h60
  text "MIL" at 12988.46,6099.92 h60
  text "19.685" at 12628,5977 h60
  text "MIN. VIA PAD SIZE:" at 11737.46,5975.8 h60
  text "MIL" at 12988.46,5975.8 h60
  text "0.05mm (2MIL)" at 12432.46,5845.9 h60
  text "MINIMUM ANNULAR RING" at 11408.23,5837.67 h60
  text "EXTERNAL" at 13140.46,5837.67 h60
  text "PER" at 11608.23,5727.55 h60
  text "IPC-D-275 CLASS 2 LEVEL C" at 11828.23,5727.54 h60
  text "MIL, HOLES" at 13316.46,5627.07 h60
  text "+/-" at 12924,5618.48 h60
  text "+/-" at 13778,5618.48 h60
  text "REGISTRATION TOLERANCES:" at 11408.23,5617.42 h60
  text "METAL" at 12608,5617.42 h60
  text "5" at 13184.2,5617.42 h60
  text "3" at 14017.2,5617.42 h60
  text "MIL" at 14133.46,5617.42 h60
  text "HOLE SIZE TOLERANCE (UNLESS OTHERWISE SPECIFIED):" at 11408.23,5519.1 h60
  text "+/-" at 13778,5516.23 h60
  text "3" at 14017.2,5515.17 h60
  text "MIL" at 14133.46,5515.17 h60
  text "MATERIAL:" at 11333.46,5377.52 h60
  text "FR-4 High Tg" at 12319.9,5249 h60
  text "X" at 12175.46,5241.01 h60
  text "FR-408" at 11754.46,5236.49 h60
  text "OTHER" at 13242.46,5236.49 h60
  text "62 MIL (1.6mm) +/-10%" at 12074.56,5093.46 h60
  text "X" at 11954.46,5091.01 h60
  text "THICKNESS:" at 11408.23,5085.24 h60
  text "OTHER" at 13359.46,5085.24 h60
  text "TOLERANCE:" at 11408.23,4946.92 h60
  text "X" at 12256.46,4946.92 h60
  text "ANSI IPC-6012 TYPE 3 CLASS 2" at 12434.48,4946.92 h60
  text "OTHER +/-" at 12434.46,4802.73 h60
  text "BOW & TWIST:" at 11408.23,4657.54 h60
  text "X" at 12256.46,4657.54 h60
  text "ANSI IPC-6012 TYPE 3 CLASS 2" at 12434.48,4657.54 h60
  text "OTHER +/-" at 12434.46,4510.85 h60
  text "DRILLING:" at 11333.46,4380.23 h60
  text "NC_DRILL FILES" at 13094.46,4275.04 h60
  text "REFERENCE:" at 11408.23,4271.1 h60
  text "X" at 12065.46,4271.01 h60
  text "AS SHOWN" at 12243.46,4271.1 h60
  text "X" at 12966.46,4271.1 h60
  text "OTHER" at 13392.46,4128.85 h60
  text "PTH COPPER THICKNESS:" at 11407.91,4125.32 h60
  text "X" at 12547.14,4125.32 h60
  text "20-30 um" at 12675.14,4125.32 h60
  text "BOARD FINISH:" at 11333.46,3977.73 h60
  text "SILKSCREEN:" at 11488.68,3867.6 h60
  text "X" at 12446.46,3867.6 h60
  text "TOP" at 12563.46,3867.6 h60
  text "X" at 12956.46,3867.6 h60
  text "BOTTOM" at 13074.46,3867.6 h60
  text "SILKSCREEN COLOR:" at 11488.68,3712.41 h60
  text "X" at 12445.46,3712.41 h60
  text "WHITE" at 12563.46,3712.41 h60
  text "OTHER" at 13074.46,3712.41 h60
  text "X" at 12576.46,3568.96 h60
  text "GREEN" at 12694.46,3568.96 h60
  text "OTHER" at 13312.46,3568.96 h60
  text "SOLDER RESIST COLOR:" at 11488.68,3562.1 h60
  text "X" at 12576.46,3414.71 h60
  text "MATTE" at 12694.46,3414.71 h60
  text "SEMI-GLOSS" at 13312,3414.07 h60
  text "IMMERSION GOLD (ENIG)" at 12394.46,3241.94 h60
  text "ENEPIG" at 13732,3234.72 h60
  text "SURFACE FINISH:" at 11333.46,3233.72 h60
  text "X" at 12216.46,3233.72 h60
  text "IMM. TIN/SILVER OR EQUIV" at 11663,3096.4 h60
  text "OTHER" at 13094.46,3092.47 h60
  text "ARRAY/PANEL:" at 11333.46,2937.09 h60
  text "CUT AND TRIM PER M1 BOARD OUTLINE" at 12394.46,2928.87 h60
  text "N.C. ROUTE" at 12394.46,2792.9 h60
  text "X" at 13082.46,2792.9 h60
  text "V. SCORE" at 13260.46,2792.9 h60
  text "CERTIFICATION:" at 11333.46,2663.77 h60
  text "MATERIALS AND WORKMANSHIP FOR ALL PCBS" at 12058.46,2663.77 h60
  text "TO MEET OR EXCEED THE REQUIREMENTS OF:" at 12058.46,2569.71 h60
  text "X" at 11695.97,2441.08 h60
  text "ANSI IPC-A-600F CLASS ->" at 11823.96,2441.08 h60
  text "X" at 13471.97,2441.08 h60
  text "2" at 13581.96,2441.08 h60
  text "1" at 13266.96,2439.58 h60
  text "3" at 13935.96,2439.58 h60
  text "X" at 12507.97,2293.39 h60
  text "RoHS" at 12635.96,2293.39 h60
  text "OTHER" at 13280.36,2293.39 h60
  text "PER ORDER" at 13677.42,2293.39 h60
  text "ALL BOARDS MUST MEET OR EXCEED UL94-V0 REQUIREMENTS." at 11361,2139.57 h60
  text "PCB MUST BEAR THE UL94V-0 UL REGISTERED MATERIAL ID NUMBER" at 11361,2023.5 h60
  text "ADDITIONAL REQUIREMENTS:" at 11333.46,1854.08 h60
  text "MICROSECTION:" at 11408.23,1746.95 h60
  text "YES" at 12313.96,1746.95 h60
  text "REQUIRED" at 13175.46,1602.62 h60
  text "BARE BOARD ELEC. TEST:" at 11408.23,1599.76 h60
  text "NONE" at 12713.96,1599.76 h60
  text "X" at 13057.46,1599.76 h60
  text "PER ORDER" at 13767.46,1599.76 h60
  text "X" at 11467.52,1450.57 h60
  text "7.874 MIL VIAS REQUIRE NON-CONDUCTIVE FILL AND PLANARIZE" at 11576.38,1394.82 h56
  text "XX MIL VIAS REQUIRE CONDUCTIVE FILL AND PLANARIZE" at 11584.38,1290.84 h60
  text "OUTER XX MIL TRACES REQUIRE 50 OHM SINGLE-ENDED IMPEDANCE" at 11583.39,1127.46 h58
  text "LAYER 2 & 3 (INNER LAYERS) XX MIL WIDE, XX MIL SPACE / TRACES REQUIRE 100 OHM DIFFERENTIAL IMPEDANCE" at 11575.39,891.74 h60
  text ".Layer_Name" at 577,-858.49 h60
M11 Gerber Information:
  lines w10: -292,-930.17 6308,-930.17 ; -292,-726.83 6310,-726.83 ; -292,-523.5 -292,-1133.5 3713,-1133.5 6310,-1133.5 6310,-523.5 -291.5,-523.5 -291.5,-1133.5 1284,-1133.5 ; 2173,-1133.5 2173,-523.5 ; 3440,-726.83 3440,-523.5 ; 4280,-726.83 4280,-523.5 ; 4902,-1140 4902,-937.17
  text "ALL ARTWORK VIEWED FROM TOP SIDE" at -228.5,-655.67 h60
  text "BOARD #:" at 2248,-655.67 h60
  text ".PRJ_Number" at 2793.5,-655.67 h60
  text "REV:" at 3638,-655.67 h60
  text ".PCB_Rev" at 3929.5,-655.67 h60
  text "SVN REV:" at 4476,-655.67 h60
  text ".VersionControl_RevNumber" at 4982,-655.67 h60
  text "LAYER NAME =" at -228.5,-858.49 h60
  text "TID #:" at 2248,-859 h60
  text ".TID" at 2793.5,-859 h60
  text "PLOT NAME =" at -228.5,-1064.34 h60
  text ".plot_File_Name" at 577,-1064.34 h60
  text "GENERATED    :" at 2250,-1064.34 h60
  text ".Print_Date" at 3119.5,-1064.34 h60
  text ".Print_Time" at 3848.5,-1064.34 h60
  text "TEXAS INSTRUMENTS" at 5113,-1064.34 h60
M12 Stackup:
  drawing of 295 lines, arcs and shapes, not listed
  text "Layer" at 9821.59,7874.94 h60
  text "Name" at 10231.51,7874.94 h60
  text "Material" at 11171.25,7874.94 h60
  text "Thickness" at 12031.02,7874.94 h60
  text "Constant" at 12680.85,7874.94 h60
  text "Board Layer Stack" at 13250.71,7874.94 h60
  text "Top Overlay" at 10231.51,7754.94 h60
  text "Top Solder" at 10231.51,7634.94 h60
  text "Solder Resist" at 11171.25,7634.94 h60
  text "0.40mil" at 12031.02,7634.94 h60
  text "3.5" at 12680.85,7634.94 h60
  text "1" at 9821.59,7514.94 h60
  text "Top Layer" at 10231.51,7514.94 h60
  text "2.80mil" at 12031.02,7514.94 h60
  text "Dielectric 1" at 10231.51,7394.94 h60
  text "FR-4 High Tg" at 11171.25,7394.94 h60
  text "8.00mil" at 12031.02,7394.94 h60
  text "4.2" at 12680.85,7394.94 h60
  text "2" at 9821.59,7274.94 h60
  text "Signal Layer 1" at 10231.51,7274.94 h60
  text "1.40mil" at 12031.02,7274.94 h60
  text "Dielectric 2" at 10231.51,7154.94 h60
  text "FR-4 High Tg" at 11171.25,7154.94 h60
  text "37.20mil" at 12031.02,7154.94 h60
  text "4.2" at 12680.85,7154.94 h60
  text "3" at 9821.59,7034.94 h60
  text "Signal Layer 2" at 10231.51,7034.94 h60
  text "1.40mil" at 12031.02,7034.94 h60
  text "Dielectric 3" at 10231.51,6914.94 h60
  text "FR-4 High Tg" at 11171.25,6914.94 h60
  text "8.00mil" at 12031.02,6914.94 h60
  text "4.2" at 12680.85,6914.94 h60
  text "4" at 9821.59,6794.94 h60
  text "Bottom Layer" at 10231.51,6794.94 h60
  text "2.80mil" at 12031.02,6794.94 h60
  text "Bottom Solder" at 10231.51,6674.94 h60
  text "Solder Resist" at 11171.25,6674.94 h60
  text "0.40mil" at 12031.02,6674.94 h60
  text "3.5" at 12680.85,6674.94 h60
  text "Bottom Overlay" at 10231.51,6554.94 h60
  text ".Layer_Name" at 577,-858.49 h60
M13 Component Bodies Top:
  text ".Layer_Name" at 577,-858.49 h60
M14 Component Bodies Bottom:
  text ".Layer_Name" at 577,-858.49 h60
M15 Courtyards Top:
  text ".Layer_Name" at 577,-858.49 h60
M16 Courtyards Bottom:
  text ".Layer_Name" at 577,-858.49 h60
Drill Drawing:
  circle w10: c5732.72,2255.88 r27.63
  lines w10: 5705.09,1979.62 5760.34,1979.62 5760.34,2034.87 5705.09,2034.87 5705.09,1979.62 ; 5705.09,2117.75 5718.9,2117.75 5718.9,2103.94 5746.53,2103.94 5746.53,2117.75 5760.34,2117.75 5760.34,2145.38 5746.53,2145.38 5746.53,2159.19 5718.9,2159.19 5718.9,2145.38 5705.09,2145.38 5705.09,2117.75 ; 5705.09,2366.39 5718.9,2366.39 5732.72,2352.58 5746.53,2366.39 5760.34,2366.39 5746.53,2380.2 5760.34,2394.02 5746.53,2394.02 5732.72,2407.83 5718.9,2394.02 5705.09,2394.02 5718.9,2380.2 5705.09,2366.39 ; 5705.09,2504.52 5732.72,2476.9 5760.34,2504.52 5732.72,2532.15 5705.09,2504.52 ; 5705.09,2601.22 5732.72,2615.03 5760.34,2601.22 5746.53,2628.84 5760.34,2656.47 5732.72,2642.66 5705.09,2656.47 5718.9,2628.84 5705.09,2601.22 ; 5705.09,2780.79 5760.34,2780.79 5732.72,2725.54 5705.09,2780.79 ; 5705.09,2849.86 5705.09,2863.67 5718.9,2877.48 5705.09,2891.3 5705.09,2905.11 5718.9,2905.11 5732.72,2891.3 5746.53,2905.11 5760.34,2905.11 5760.34,2891.3 5746.53,2877.48 5760.34,2863.67 5760.34,2849.86 5746.53,2849.86 5732.72,2863.67 5718.9,2849.86 5705.09,2849.86 ; 5705.09,2974.18 5760.34,2974.18 5760.34,3029.43 5705.09,3029.43 5705.09,2974.18 ; 5716.14,2985.23 5749.29,2985.23 5749.29,3018.38 5716.14,3018.38 5716.14,2985.23
  lines w12: 5655,1942.32 8840,1942.32 ; 5655,3061.2 8840,3061.2 ; 5992.86,1818 5992.86,3185.52 ; 6322.14,1818 6322.14,3185.52 ; 6914.94,1818 6914.94,3185.52 ; 7174.08,1818 7174.08,3185.52 ; 7549.24,1818 7549.24,3185.52 ; 8273.57,1818 8273.57,3185.52 ; 5655,1818 8840,1818 8840,3185.52 5655,3185.52 5655,1818
  text "Symbol" at 5729.59,3098.5 h72
  text "Count" at 6030.16,3098.5 h72
  text "Hole Size" at 6359.44,3098.5 h72
  text "Plated" at 6952.23,3098.5 h72
  text "Hole Type" at 7211.38,3098.5 h72
  text "Drill Layer Pair" at 7586.53,3098.5 h72
  text "Hole Tolerance" at 8310.86,3098.5 h72
  text "1106" at 6030.16,2974.18 h60
  text "7.87mil (0.200mm)" at 6359.44,2974.18 h60
  text "PTH" at 6952.23,2974.18 h60
  text "Round" at 7211.38,2974.18 h60
  text "Top Layer - Bottom Layer" at 7586.53,2974.18 h60
  text "4" at 6030.16,2849.86 h60
  text "16.00mil (0.406mm)" at 6359.44,2849.86 h60
  text "PTH" at 6952.23,2849.86 h60
  text "Round" at 7211.38,2849.86 h60
  text "Top Layer - Bottom Layer" at 7586.53,2849.86 h60
  text "19" at 6030.16,2725.54 h60
  text "40.00mil (1.016mm)" at 6359.44,2725.54 h60
  text "PTH" at 6952.23,2725.54 h60
  text "Round" at 7211.38,2725.54 h60
  text "Top Layer - Bottom Layer" at 7586.53,2725.54 h60
  text "6" at 6030.16,2601.22 h60
  text "40.16mil (1.020mm)" at 6359.44,2601.22 h60
  text "PTH" at 6952.23,2601.22 h60
  text "Round" at 7211.38,2601.22 h60
  text "Top Layer - Bottom Layer" at 7586.53,2601.22 h60
  text "5" at 6030.16,2476.9 h60
  text "43.31mil (1.100mm)" at 6359.44,2476.9 h60
  text "PTH" at 6952.23,2476.9 h60
  text "Round" at 7211.38,2476.9 h60
  text "Top Layer - Bottom Layer" at 7586.53,2476.9 h60
  text "+/-1.97mil" at 8310.86,2476.9 h60
  text "35" at 6030.16,2352.58 h60
  text "45.28mil (1.150mm)" at 6359.44,2352.58 h60
  text "PTH" at 6952.23,2352.58 h60
  text "Round" at 7211.38,2352.58 h60
  text "Top Layer - Bottom Layer" at 7586.53,2352.58 h60
  text "8" at 6030.16,2228.26 h60
  text "63.00mil (1.600mm)" at 6359.44,2228.26 h60
  text "PTH" at 6952.23,2228.26 h60
  text "Round" at 7211.38,2228.26 h60
  text "Top Layer - Bottom Layer" at 7586.53,2228.26 h60
  text "4" at 6030.16,2103.94 h60
  text "125.98mil (3.200mm)" at 6359.44,2103.94 h60
  text "PTH" at 6952.23,2103.94 h60
  text "Round" at 7211.38,2103.94 h60
  text "Top Layer - Bottom Layer" at 7586.53,2103.94 h60
  text "4" at 6030.16,1979.62 h60
  text "270.00mil (6.858mm)" at 6359.44,1979.62 h60
  text "PTH" at 6952.23,1979.62 h60
  text "Round" at 7211.38,1979.62 h60
  text "Top Layer - Bottom Layer" at 7586.53,1979.62 h60
  text "1191 Total" at 6030.16,1855.3 h60
  text ".Layer_Name" at 577,-858.49 h60
M17 Embedded Cavity:
  text ".Layer_Name" at 577,-858.49 h60
M18 Embedded Assembly:
  text ".Layer_Name" at 577,-858.49 h60
M19 Embedded Keepout:
  text ".Layer_Name" at 577,-858.49 h60

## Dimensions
0,0 to 0,3200 on M2 Board Dimensions
0,0 to 5500,0 on M2 Board Dimensions
0,-400 to 1000,-400 on M2 Board Dimensions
